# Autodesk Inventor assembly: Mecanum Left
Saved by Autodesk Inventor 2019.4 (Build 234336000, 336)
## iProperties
Created: 2020-06
Part Number: Mecanum Left
Document SubType Name: Assembly
Designer: Administrator
Title: Mecanum Left v5
Author: Administrator
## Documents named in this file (4)
- c:\worker\convert-fusion-r05\tmp\job-1\11\output\files\909afe3d-74f7-4212-acfe-dd169c17575c\770aaded-88a2-40d0-a11e-bcc575a1c5ec.iam
- c:\worker\convert-fusion-r05\tmp\job-1\11\output\files\909afe3d-74f7-4212-acfe-dd169c17575c\Side1.ipt
- c:\worker\convert-fusion-r05\tmp\job-1\11\output\files\909afe3d-74f7-4212-acfe-dd169c17575c\Side 2.ipt
- c:\worker\convert-fusion-r05\tmp\job-1\11\output\files\909afe3d-74f7-4212-acfe-dd169c17575c\Roller v3.ipt
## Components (11 placed, 3 different names)
1. Side1:1
2. Side 2:1
3. Roller v3:1
4. Roller v3:2
5. Roller v3:3
6. Roller v3:4
7. Roller v3:5
8. Roller v3:6
9. Roller v3:7
10. Roller v3:8
11. Roller v3:9
